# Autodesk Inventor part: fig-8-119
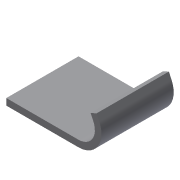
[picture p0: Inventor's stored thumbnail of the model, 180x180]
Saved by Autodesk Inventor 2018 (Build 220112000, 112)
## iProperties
Created: 2009-09
Part Number: fig-8-119
Document SubType Name: Modeling
Designer: Sham
Density: 1 g/cm^3
Material: Generic
Appearance: Default
Author: Sham
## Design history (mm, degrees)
sketch "Sketch1"
  geometry: L1 (-33.976, 22)-(0, 22); L2 (0, 22)-(0, 0); L3 (0, 0)-(-33.976, 0); L4 (-33.976, 0)-(-33.976, 22)
  constraints: 8 end point, 2 parallel, 1 horizontal, 1 perpendicular
extrude "Extrusion1" new body sketch "Sketch1" distance "d0" = 2; taper "d1" = 0 deg
sketch "Sketch2"
  geometry: L1 (-12, 22)-(-12, 0)
  constraints: 2 end point
feature "Bend Part1" sketch "Sketch2" dims "d2" = 5, "d4" = 10
body "Solid1"
